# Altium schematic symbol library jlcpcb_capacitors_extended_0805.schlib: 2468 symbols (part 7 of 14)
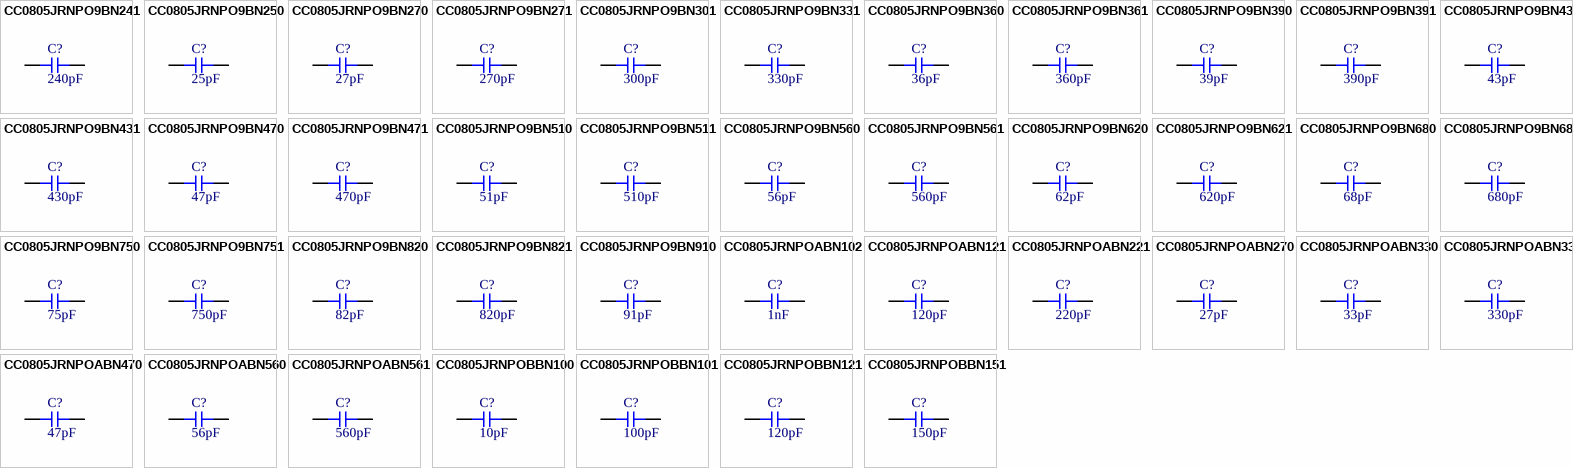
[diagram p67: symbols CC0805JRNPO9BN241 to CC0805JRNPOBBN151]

## CC0805JRNPO9BN511
designator C?  Capacitance: 510pF  (hidden comment: *)
Capacitor, Ceramic (MLCC), 510pF, ±5%, 50V, NP0, ±5%, SMD 0805; Manufacturer: YAGEO; Manufacturer Part Number: CC0805JRNPO9BN511
footprint CAP-0805 (0805 (2012M) Capacitor)
pins: 1, 2

## CC0805JRNPO9BN560
designator C?  Capacitance: 56pF  (hidden comment: *)
Capacitor, Ceramic (MLCC), 56pF, ±5%, 50V, NP0, ±5%, SMD 0805; Manufacturer: YAGEO; Manufacturer Part Number: CC0805JRNPO9BN560
footprint CAP-0805 (0805 (2012M) Capacitor)
pins: 1, 2

## CC0805JRNPO9BN561
designator C?  Capacitance: 560pF  (hidden comment: *)
Capacitor, Ceramic (MLCC), 560pF, ±5%, 50V, NP0, ±5%, SMD 0805; Manufacturer: YAGEO; Manufacturer Part Number: CC0805JRNPO9BN561
footprint CAP-0805 (0805 (2012M) Capacitor)
pins: 1, 2

## CC0805JRNPO9BN620
designator C?  Capacitance: 62pF  (hidden comment: *)
Capacitor, Ceramic (MLCC), 62pF, ±5%, 50V, NP0, ±5%, SMD 0805; Manufacturer: YAGEO; Manufacturer Part Number: CC0805JRNPO9BN620
footprint CAP-0805 (0805 (2012M) Capacitor)
pins: 1, 2

## CC0805JRNPO9BN621
designator C?  Capacitance: 620pF  (hidden comment: *)
Capacitor, Ceramic (MLCC), 620pF, ±5%, 50V, NP0, ±5%, SMD 0805; Manufacturer: YAGEO; Manufacturer Part Number: CC0805JRNPO9BN621
footprint CAP-0805 (0805 (2012M) Capacitor)
pins: 1, 2

## CC0805JRNPO9BN680
designator C?  Capacitance: 68pF  (hidden comment: *)
Capacitor, Ceramic (MLCC), 68pF, ±5%, 50V, NP0, ±5%, SMD 0805; Manufacturer: YAGEO; Manufacturer Part Number: CC0805JRNPO9BN680
footprint CAP-0805 (0805 (2012M) Capacitor)
pins: 1, 2

## CC0805JRNPO9BN681
designator C?  Capacitance: 680pF  (hidden comment: *)
Capacitor, Ceramic (MLCC), 680pF, ±5%, 50V, NP0, ±5%, SMD 0805; Manufacturer: YAGEO; Manufacturer Part Number: CC0805JRNPO9BN681
footprint CAP-0805 (0805 (2012M) Capacitor)
pins: 1, 2

## CC0805JRNPO9BN750
designator C?  Capacitance: 75pF  (hidden comment: *)
Capacitor, Ceramic (MLCC), 75pF, ±5%, 50V, NP0, ±5%, SMD 0805; Manufacturer: YAGEO; Manufacturer Part Number: CC0805JRNPO9BN750
footprint CAP-0805 (0805 (2012M) Capacitor)
pins: 1, 2

## CC0805JRNPO9BN751
designator C?  Capacitance: 750pF  (hidden comment: *)
Capacitor, Ceramic (MLCC), 750pF, ±5%, 50V, NP0, ±5%, SMD 0805; Manufacturer: YAGEO; Manufacturer Part Number: CC0805JRNPO9BN751
footprint CAP-0805 (0805 (2012M) Capacitor)
pins: 1, 2

## CC0805JRNPO9BN820
designator C?  Capacitance: 82pF  (hidden comment: *)
Capacitor, Ceramic (MLCC), 82pF, ±5%, 50V, NP0, ±5%, SMD 0805; Manufacturer: YAGEO; Manufacturer Part Number: CC0805JRNPO9BN820
footprint CAP-0805 (0805 (2012M) Capacitor)
pins: 1, 2

## CC0805JRNPO9BN821
designator C?  Capacitance: 820pF  (hidden comment: *)
Capacitor, Ceramic (MLCC), 820pF, ±5%, 50V, NP0, ±5%, SMD 0805; Manufacturer: YAGEO; Manufacturer Part Number: CC0805JRNPO9BN821
footprint CAP-0805 (0805 (2012M) Capacitor)
pins: 1, 2

## CC0805JRNPO9BN910
designator C?  Capacitance: 91pF  (hidden comment: *)
Capacitor, Ceramic (MLCC), 91pF, ±5%, 50V, NP0, ±5%, SMD 0805; Manufacturer: YAGEO; Manufacturer Part Number: CC0805JRNPO9BN910
footprint CAP-0805 (0805 (2012M) Capacitor)
pins: 1, 2

## CC0805JRNPOABN102
designator C?  Capacitance: 1nF  (hidden comment: *)
Capacitor, Ceramic (MLCC), 1nF, ±5%, 200V, NP0, ±5%, SMD 0805; Manufacturer: YAGEO; Manufacturer Part Number: CC0805JRNPOABN102
footprint CAP-0805 (0805 (2012M) Capacitor)
pins: 1, 2

## CC0805JRNPOABN121
designator C?  Capacitance: 120pF  (hidden comment: *)
Capacitor, Ceramic (MLCC), 120pF, ±5%, 200V, NP0, ±5%, SMD 0805; Manufacturer: YAGEO; Manufacturer Part Number: CC0805JRNPOABN121
footprint CAP-0805 (0805 (2012M) Capacitor)
pins: 1, 2

## CC0805JRNPOABN221
designator C?  Capacitance: 220pF  (hidden comment: *)
Capacitor, Ceramic (MLCC), 220pF, ±5%, 200V, NP0, ±5%, SMD 0805; Manufacturer: YAGEO; Manufacturer Part Number: CC0805JRNPOABN221
footprint CAP-0805 (0805 (2012M) Capacitor)
pins: 1, 2

## CC0805JRNPOABN270
designator C?  Capacitance: 27pF  (hidden comment: *)
Capacitor, Ceramic (MLCC), 27pF, ±5%, 200V, NP0, ±5%, SMD 0805; Manufacturer: YAGEO; Manufacturer Part Number: CC0805JRNPOABN270
footprint CAP-0805 (0805 (2012M) Capacitor)
pins: 1, 2

## CC0805JRNPOABN330
designator C?  Capacitance: 33pF  (hidden comment: *)
Capacitor, Ceramic (MLCC), 33pF, ±5%, 200V, NP0, ±5%, SMD 0805; Manufacturer: YAGEO; Manufacturer Part Number: CC0805JRNPOABN330
footprint CAP-0805 (0805 (2012M) Capacitor)
pins: 1, 2

## CC0805JRNPOABN331
designator C?  Capacitance: 330pF  (hidden comment: *)
Capacitor, Ceramic (MLCC), 330pF, ±5%, 200V, NP0, ±5%, SMD 0805; Manufacturer: YAGEO; Manufacturer Part Number: CC0805JRNPOABN331
footprint CAP-0805 (0805 (2012M) Capacitor)
pins: 1, 2

## CC0805JRNPOABN470
designator C?  Capacitance: 47pF  (hidden comment: *)
Capacitor, Ceramic (MLCC), 47pF, ±5%, 200V, NP0, ±5%, SMD 0805; Manufacturer: YAGEO; Manufacturer Part Number: CC0805JRNPOABN470
footprint CAP-0805 (0805 (2012M) Capacitor)
pins: 1, 2

## CC0805JRNPOABN560
designator C?  Capacitance: 56pF  (hidden comment: *)
Capacitor, Ceramic (MLCC), 56pF, ±5%, 200V, NP0, ±5%, SMD 0805; Manufacturer: YAGEO; Manufacturer Part Number: CC0805JRNPOABN560
footprint CAP-0805 (0805 (2012M) Capacitor)
pins: 1, 2

## CC0805JRNPOABN561
designator C?  Capacitance: 560pF  (hidden comment: *)
Capacitor, Ceramic (MLCC), 560pF, ±5%, 200V, NP0, ±5%, SMD 0805; Manufacturer: YAGEO; Manufacturer Part Number: CC0805JRNPOABN561
footprint CAP-0805 (0805 (2012M) Capacitor)
pins: 1, 2

## CC0805JRNPOBBN100
designator C?  Capacitance: 10pF  (hidden comment: *)
Capacitor, Ceramic (MLCC), 10pF, ±5%, 500V, NP0, ±5%, SMD 0805; Manufacturer: YAGEO; Manufacturer Part Number: CC0805JRNPOBBN100
footprint CAP-0805 (0805 (2012M) Capacitor)
pins: 1, 2

## CC0805JRNPOBBN101
designator C?  Capacitance: 100pF  (hidden comment: *)
Capacitor, Ceramic (MLCC), 100pF, ±5%, 500V, NP0, ±5%, SMD 0805; Manufacturer: YAGEO; Manufacturer Part Number: CC0805JRNPOBBN101
footprint CAP-0805 (0805 (2012M) Capacitor)
pins: 1, 2

## CC0805JRNPOBBN121
designator C?  Capacitance: 120pF  (hidden comment: *)
Capacitor, Ceramic (MLCC), 120pF, ±5%, 500V, NP0, ±5%, SMD 0805; Manufacturer: YAGEO; Manufacturer Part Number: CC0805JRNPOBBN121
footprint CAP-0805 (0805 (2012M) Capacitor)
pins: 1, 2

## CC0805JRNPOBBN151
designator C?  Capacitance: 150pF  (hidden comment: *)
Capacitor, Ceramic (MLCC), 150pF, ±5%, 500V, NP0, ±5%, SMD 0805; Manufacturer: YAGEO; Manufacturer Part Number: CC0805JRNPOBBN151
footprint CAP-0805 (0805 (2012M) Capacitor)
pins: 1, 2

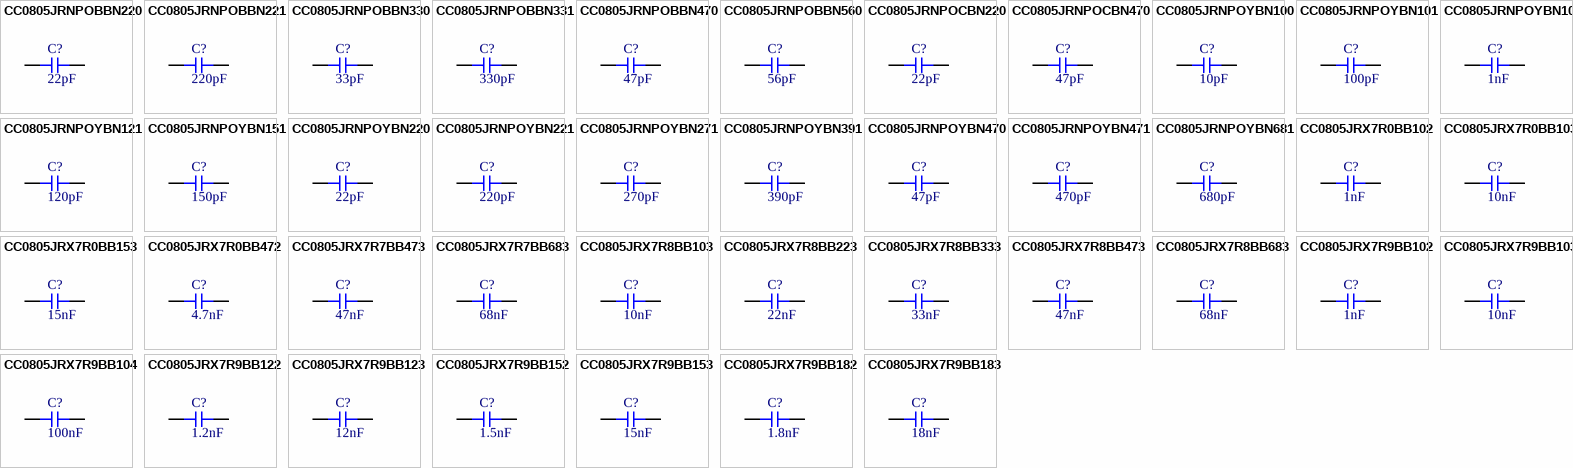
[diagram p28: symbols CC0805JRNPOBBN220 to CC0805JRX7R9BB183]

## CC0805JRNPOBBN220
designator C?  Capacitance: 22pF  (hidden comment: *)
Capacitor, Ceramic (MLCC), 22pF, ±5%, 500V, NP0, ±5%, SMD 0805; Manufacturer: YAGEO; Manufacturer Part Number: CC0805JRNPOBBN220
footprint CAP-0805 (0805 (2012M) Capacitor)
pins: 1, 2

## CC0805JRNPOBBN221
designator C?  Capacitance: 220pF  (hidden comment: *)
Capacitor, Ceramic (MLCC), 220pF, ±5%, 500V, NP0, ±5%, SMD 0805; Manufacturer: YAGEO; Manufacturer Part Number: CC0805JRNPOBBN221
footprint CAP-0805 (0805 (2012M) Capacitor)
pins: 1, 2

## CC0805JRNPOBBN330
designator C?  Capacitance: 33pF  (hidden comment: *)
Capacitor, Ceramic (MLCC), 33pF, ±5%, 500V, NP0, ±5%, SMD 0805; Manufacturer: YAGEO; Manufacturer Part Number: CC0805JRNPOBBN330
footprint CAP-0805 (0805 (2012M) Capacitor)
pins: 1, 2

## CC0805JRNPOBBN331
designator C?  Capacitance: 330pF  (hidden comment: *)
Capacitor, Ceramic (MLCC), 330pF, ±5%, 500V, NP0, ±5%, SMD 0805; Manufacturer: YAGEO; Manufacturer Part Number: CC0805JRNPOBBN331
footprint CAP-0805 (0805 (2012M) Capacitor)
pins: 1, 2

## CC0805JRNPOBBN470
designator C?  Capacitance: 47pF  (hidden comment: *)
Capacitor, Ceramic (MLCC), 47pF, ±5%, 500V, NP0, ±5%, SMD 0805; Manufacturer: YAGEO; Manufacturer Part Number: CC0805JRNPOBBN470
footprint CAP-0805 (0805 (2012M) Capacitor)
pins: 1, 2

## CC0805JRNPOBBN560
designator C?  Capacitance: 56pF  (hidden comment: *)
Capacitor, Ceramic (MLCC), 56pF, ±5%, 500V, NP0, ±5%, SMD 0805; Manufacturer: YAGEO; Manufacturer Part Number: CC0805JRNPOBBN560
footprint CAP-0805 (0805 (2012M) Capacitor)
pins: 1, 2

## CC0805JRNPOCBN220
designator C?  Capacitance: 22pF  (hidden comment: *)
Capacitor, Ceramic (MLCC), 22pF, ±5%, 1kV, NP0, ±5%, SMD 0805; Manufacturer: YAGEO; Manufacturer Part Number: CC0805JRNPOCBN220
footprint CAP-0805 (0805 (2012M) Capacitor)
pins: 1, 2

## CC0805JRNPOCBN470
designator C?  Capacitance: 47pF  (hidden comment: *)
Capacitor, Ceramic (MLCC), 47pF, ±5%, 1kV, NP0, ±5%, SMD 0805; Manufacturer: YAGEO; Manufacturer Part Number: CC0805JRNPOCBN470
footprint CAP-0805 (0805 (2012M) Capacitor)
pins: 1, 2

## CC0805JRNPOYBN100
designator C?  Capacitance: 10pF  (hidden comment: *)
Capacitor, Ceramic (MLCC), 10pF, ±5%, 250V, NP0, ±5%, SMD 0805; Manufacturer: YAGEO; Manufacturer Part Number: CC0805JRNPOYBN100
footprint CAP-0805 (0805 (2012M) Capacitor)
pins: 1, 2

## CC0805JRNPOYBN101
designator C?  Capacitance: 100pF  (hidden comment: *)
Capacitor, Ceramic (MLCC), 100pF, ±5%, 250V, NP0, ±5%, SMD 0805; Manufacturer: YAGEO; Manufacturer Part Number: CC0805JRNPOYBN101
footprint CAP-0805 (0805 (2012M) Capacitor)
pins: 1, 2

## CC0805JRNPOYBN102
designator C?  Capacitance: 1nF  (hidden comment: *)
Capacitor, Ceramic (MLCC), 1nF, ±5%, 250V, NP0, ±5%, SMD 0805; Manufacturer: YAGEO; Manufacturer Part Number: CC0805JRNPOYBN102
footprint CAP-0805 (0805 (2012M) Capacitor)
pins: 1, 2

## CC0805JRNPOYBN121
designator C?  Capacitance: 120pF  (hidden comment: *)
Capacitor, Ceramic (MLCC), 120pF, ±5%, 250V, NP0, ±5%, SMD 0805; Manufacturer: YAGEO; Manufacturer Part Number: CC0805JRNPOYBN121
footprint CAP-0805 (0805 (2012M) Capacitor)
pins: 1, 2

## CC0805JRNPOYBN151
designator C?  Capacitance: 150pF  (hidden comment: *)
Capacitor, Ceramic (MLCC), 150pF, ±5%, 250V, NP0, ±5%, SMD 0805; Manufacturer: YAGEO; Manufacturer Part Number: CC0805JRNPOYBN151
footprint CAP-0805 (0805 (2012M) Capacitor)
pins: 1, 2

## CC0805JRNPOYBN220
designator C?  Capacitance: 22pF  (hidden comment: *)
Capacitor, Ceramic (MLCC), 22pF, ±5%, 250V, NP0, ±5%, SMD 0805; Manufacturer: YAGEO; Manufacturer Part Number: CC0805JRNPOYBN220
footprint CAP-0805 (0805 (2012M) Capacitor)
pins: 1, 2

## CC0805JRNPOYBN221
designator C?  Capacitance: 220pF  (hidden comment: *)
Capacitor, Ceramic (MLCC), 220pF, ±5%, 250V, NP0, ±5%, SMD 0805; Manufacturer: YAGEO; Manufacturer Part Number: CC0805JRNPOYBN221
footprint CAP-0805 (0805 (2012M) Capacitor)
pins: 1, 2

## CC0805JRNPOYBN271
designator C?  Capacitance: 270pF  (hidden comment: *)
Capacitor, Ceramic (MLCC), 270pF, ±5%, 250V, NP0, ±5%, SMD 0805; Manufacturer: YAGEO; Manufacturer Part Number: CC0805JRNPOYBN271
footprint CAP-0805 (0805 (2012M) Capacitor)
pins: 1, 2

## CC0805JRNPOYBN391
designator C?  Capacitance: 390pF  (hidden comment: *)
Capacitor, Ceramic (MLCC), 390pF, ±5%, 250V, NP0, ±5%, SMD 0805; Manufacturer: YAGEO; Manufacturer Part Number: CC0805JRNPOYBN391
footprint CAP-0805 (0805 (2012M) Capacitor)
pins: 1, 2

## CC0805JRNPOYBN470
designator C?  Capacitance: 47pF  (hidden comment: *)
Capacitor, Ceramic (MLCC), 47pF, ±5%, 250V, NP0, ±5%, SMD 0805; Manufacturer: YAGEO; Manufacturer Part Number: CC0805JRNPOYBN470
footprint CAP-0805 (0805 (2012M) Capacitor)
pins: 1, 2

## CC0805JRNPOYBN471
designator C?  Capacitance: 470pF  (hidden comment: *)
Capacitor, Ceramic (MLCC), 470pF, ±5%, 250V, NP0, ±5%, SMD 0805; Manufacturer: YAGEO; Manufacturer Part Number: CC0805JRNPOYBN471
footprint CAP-0805 (0805 (2012M) Capacitor)
pins: 1, 2

## CC0805JRNPOYBN681
designator C?  Capacitance: 680pF  (hidden comment: *)
Capacitor, Ceramic (MLCC), 680pF, ±5%, 250V, NP0, ±5%, SMD 0805; Manufacturer: YAGEO; Manufacturer Part Number: CC0805JRNPOYBN681
footprint CAP-0805 (0805 (2012M) Capacitor)
pins: 1, 2

## CC0805JRX7R0BB102
designator C?  Capacitance: 1nF  (hidden comment: *)
Capacitor, Ceramic (MLCC), 1nF, ±5%, 100V, X7R, ±5%, SMD 0805; Manufacturer: YAGEO; Manufacturer Part Number: CC0805JRX7R0BB102
footprint CAP-0805 (0805 (2012M) Capacitor)
pins: 1, 2

## CC0805JRX7R0BB103
designator C?  Capacitance: 10nF  (hidden comment: *)
Capacitor, Ceramic (MLCC), 10nF, ±5%, 100V, X7R, ±5%, SMD 0805; Manufacturer: YAGEO; Manufacturer Part Number: CC0805JRX7R0BB103
footprint CAP-0805 (0805 (2012M) Capacitor)
pins: 1, 2

## CC0805JRX7R0BB153
designator C?  Capacitance: 15nF  (hidden comment: *)
Capacitor, Ceramic (MLCC), 15nF, ±5%, 100V, X7R, ±5%, SMD 0805; Manufacturer: YAGEO; Manufacturer Part Number: CC0805JRX7R0BB153
footprint CAP-0805 (0805 (2012M) Capacitor)
pins: 1, 2

## CC0805JRX7R0BB472
designator C?  Capacitance: 4.7nF  (hidden comment: *)
Capacitor, Ceramic (MLCC), 4.7nF, ±5%, 100V, X7R, ±5%, SMD 0805; Manufacturer: YAGEO; Manufacturer Part Number: CC0805JRX7R0BB472
footprint CAP-0805 (0805 (2012M) Capacitor)
pins: 1, 2

## CC0805JRX7R7BB473
designator C?  Capacitance: 47nF  (hidden comment: *)
Capacitor, Ceramic (MLCC), 47nF, ±5%, 16V, X7R, ±5%, SMD 0805; Manufacturer: YAGEO; Manufacturer Part Number: CC0805JRX7R7BB473
footprint CAP-0805 (0805 (2012M) Capacitor)
pins: 1, 2

## CC0805JRX7R7BB683
designator C?  Capacitance: 68nF  (hidden comment: *)
Capacitor, Ceramic (MLCC), 68nF, ±5%, 16V, X7R, ±5%, SMD 0805; Manufacturer: YAGEO; Manufacturer Part Number: CC0805JRX7R7BB683
footprint CAP-0805 (0805 (2012M) Capacitor)
pins: 1, 2

## CC0805JRX7R8BB103
designator C?  Capacitance: 10nF  (hidden comment: *)
Capacitor, Ceramic (MLCC), 10nF, ±5%, 25V, X7R, ±5%, SMD 0805; Manufacturer: YAGEO; Manufacturer Part Number: CC0805JRX7R8BB103
footprint CAP-0805 (0805 (2012M) Capacitor)
pins: 1, 2

## CC0805JRX7R8BB223
designator C?  Capacitance: 22nF  (hidden comment: *)
Capacitor, Ceramic (MLCC), 22nF, ±5%, 25V, X7R, ±5%, SMD 0805; Manufacturer: YAGEO; Manufacturer Part Number: CC0805JRX7R8BB223
footprint CAP-0805 (0805 (2012M) Capacitor)
pins: 1, 2

## CC0805JRX7R8BB333
designator C?  Capacitance: 33nF  (hidden comment: *)
Capacitor, Ceramic (MLCC), 33nF, ±5%, 25V, X7R, ±5%, SMD 0805; Manufacturer: YAGEO; Manufacturer Part Number: CC0805JRX7R8BB333
footprint CAP-0805 (0805 (2012M) Capacitor)
pins: 1, 2

## CC0805JRX7R8BB473
designator C?  Capacitance: 47nF  (hidden comment: *)
Capacitor, Ceramic (MLCC), 47nF, ±5%, 25V, X7R, ±5%, SMD 0805; Manufacturer: YAGEO; Manufacturer Part Number: CC0805JRX7R8BB473
footprint CAP-0805 (0805 (2012M) Capacitor)
pins: 1, 2

## CC0805JRX7R8BB683
designator C?  Capacitance: 68nF  (hidden comment: *)
Capacitor, Ceramic (MLCC), 68nF, ±5%, 25V, X7R, ±5%, SMD 0805; Manufacturer: YAGEO; Manufacturer Part Number: CC0805JRX7R8BB683
footprint CAP-0805 (0805 (2012M) Capacitor)
pins: 1, 2

## CC0805JRX7R9BB102
designator C?  Capacitance: 1nF  (hidden comment: *)
Capacitor, Ceramic (MLCC), 1nF, ±5%, 50V, X7R, ±5%, SMD 0805; Manufacturer: YAGEO; Manufacturer Part Number: CC0805JRX7R9BB102
footprint CAP-0805 (0805 (2012M) Capacitor)
pins: 1, 2

## CC0805JRX7R9BB103
designator C?  Capacitance: 10nF  (hidden comment: *)
Capacitor, Ceramic (MLCC), 10nF, ±5%, 50V, X7R, ±5%, SMD 0805; Manufacturer: YAGEO; Manufacturer Part Number: CC0805JRX7R9BB103
footprint CAP-0805 (0805 (2012M) Capacitor)
pins: 1, 2

## CC0805JRX7R9BB104
designator C?  Capacitance: 100nF  (hidden comment: *)
Capacitor, Ceramic (MLCC), 100nF, ±5%, 50V, X7R, ±5%, SMD 0805; Manufacturer: YAGEO; Manufacturer Part Number: CC0805JRX7R9BB104
footprint CAP-0805 (0805 (2012M) Capacitor)
pins: 1, 2

## CC0805JRX7R9BB122
designator C?  Capacitance: 1.2nF  (hidden comment: *)
Capacitor, Ceramic (MLCC), 1.2nF, ±5%, 50V, X7R, ±5%, SMD 0805; Manufacturer: YAGEO; Manufacturer Part Number: CC0805JRX7R9BB122
footprint CAP-0805 (0805 (2012M) Capacitor)
pins: 1, 2

## CC0805JRX7R9BB123
designator C?  Capacitance: 12nF  (hidden comment: *)
Capacitor, Ceramic (MLCC), 12nF, ±5%, 50V, X7R, ±5%, SMD 0805; Manufacturer: YAGEO; Manufacturer Part Number: CC0805JRX7R9BB123
footprint CAP-0805 (0805 (2012M) Capacitor)
pins: 1, 2

## CC0805JRX7R9BB152
designator C?  Capacitance: 1.5nF  (hidden comment: *)
Capacitor, Ceramic (MLCC), 1.5nF, ±5%, 50V, X7R, ±5%, SMD 0805; Manufacturer: YAGEO; Manufacturer Part Number: CC0805JRX7R9BB152
footprint CAP-0805 (0805 (2012M) Capacitor)
pins: 1, 2

## CC0805JRX7R9BB153
designator C?  Capacitance: 15nF  (hidden comment: *)
Capacitor, Ceramic (MLCC), 15nF, ±5%, 50V, X7R, ±5%, SMD 0805; Manufacturer: YAGEO; Manufacturer Part Number: CC0805JRX7R9BB153
footprint CAP-0805 (0805 (2012M) Capacitor)
pins: 1, 2

## CC0805JRX7R9BB182
designator C?  Capacitance: 1.8nF  (hidden comment: *)
Capacitor, Ceramic (MLCC), 1.8nF, ±5%, 50V, X7R, ±5%, SMD 0805; Manufacturer: YAGEO; Manufacturer Part Number: CC0805JRX7R9BB182
footprint CAP-0805 (0805 (2012M) Capacitor)
pins: 1, 2

## CC0805JRX7R9BB183
designator C?  Capacitance: 18nF  (hidden comment: *)
Capacitor, Ceramic (MLCC), 18nF, ±5%, 50V, X7R, ±5%, SMD 0805; Manufacturer: YAGEO; Manufacturer Part Number: CC0805JRX7R9BB183
footprint CAP-0805 (0805 (2012M) Capacitor)
pins: 1, 2

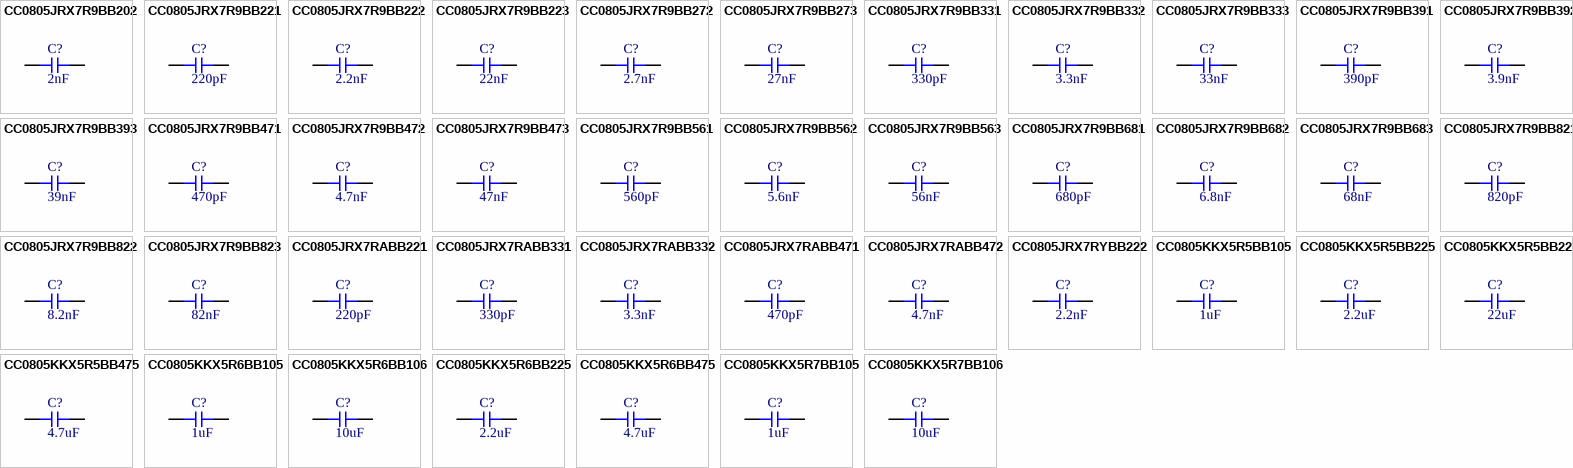
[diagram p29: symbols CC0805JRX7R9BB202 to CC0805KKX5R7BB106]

## CC0805JRX7R9BB202
designator C?  Capacitance: 2nF  (hidden comment: *)
Capacitor, Ceramic (MLCC), 2nF, ±5%, 50V, X7R, ±5%, SMD 0805; Manufacturer: YAGEO; Manufacturer Part Number: CC0805JRX7R9BB202
footprint CAP-0805 (0805 (2012M) Capacitor)
pins: 1, 2

## CC0805JRX7R9BB221
designator C?  Capacitance: 220pF  (hidden comment: *)
Capacitor, Ceramic (MLCC), 220pF, ±5%, 50V, X7R, ±5%, SMD 0805; Manufacturer: YAGEO; Manufacturer Part Number: CC0805JRX7R9BB221
footprint CAP-0805 (0805 (2012M) Capacitor)
pins: 1, 2

## CC0805JRX7R9BB222
designator C?  Capacitance: 2.2nF  (hidden comment: *)
Capacitor, Ceramic (MLCC), 2.2nF, ±5%, 50V, X7R, ±5%, SMD 0805; Manufacturer: YAGEO; Manufacturer Part Number: CC0805JRX7R9BB222
footprint CAP-0805 (0805 (2012M) Capacitor)
pins: 1, 2

## CC0805JRX7R9BB223
designator C?  Capacitance: 22nF  (hidden comment: *)
Capacitor, Ceramic (MLCC), 22nF, ±5%, 50V, X7R, ±5%, SMD 0805; Manufacturer: YAGEO; Manufacturer Part Number: CC0805JRX7R9BB223
footprint CAP-0805 (0805 (2012M) Capacitor)
pins: 1, 2

## CC0805JRX7R9BB272
designator C?  Capacitance: 2.7nF  (hidden comment: *)
Capacitor, Ceramic (MLCC), 2.7nF, ±5%, 50V, X7R, ±5%, SMD 0805; Manufacturer: YAGEO; Manufacturer Part Number: CC0805JRX7R9BB272
footprint CAP-0805 (0805 (2012M) Capacitor)
pins: 1, 2

## CC0805JRX7R9BB273
designator C?  Capacitance: 27nF  (hidden comment: *)
Capacitor, Ceramic (MLCC), 27nF, ±5%, 50V, X7R, ±5%, SMD 0805; Manufacturer: YAGEO; Manufacturer Part Number: CC0805JRX7R9BB273
footprint CAP-0805 (0805 (2012M) Capacitor)
pins: 1, 2

## CC0805JRX7R9BB331
designator C?  Capacitance: 330pF  (hidden comment: *)
Capacitor, Ceramic (MLCC), 330pF, ±5%, 50V, X7R, ±5%, SMD 0805; Manufacturer: YAGEO; Manufacturer Part Number: CC0805JRX7R9BB331
footprint CAP-0805 (0805 (2012M) Capacitor)
pins: 1, 2

## CC0805JRX7R9BB332
designator C?  Capacitance: 3.3nF  (hidden comment: *)
Capacitor, Ceramic (MLCC), 3.3nF, ±5%, 50V, X7R, ±5%, SMD 0805; Manufacturer: YAGEO; Manufacturer Part Number: CC0805JRX7R9BB332
footprint CAP-0805 (0805 (2012M) Capacitor)
pins: 1, 2

## CC0805JRX7R9BB333
designator C?  Capacitance: 33nF  (hidden comment: *)
Capacitor, Ceramic (MLCC), 33nF, ±5%, 50V, X7R, ±5%, SMD 0805; Manufacturer: YAGEO; Manufacturer Part Number: CC0805JRX7R9BB333
footprint CAP-0805 (0805 (2012M) Capacitor)
pins: 1, 2

## CC0805JRX7R9BB391
designator C?  Capacitance: 390pF  (hidden comment: *)
Capacitor, Ceramic (MLCC), 390pF, ±5%, 50V, X7R, ±5%, SMD 0805; Manufacturer: YAGEO; Manufacturer Part Number: CC0805JRX7R9BB391
footprint CAP-0805 (0805 (2012M) Capacitor)
pins: 1, 2

## CC0805JRX7R9BB392
designator C?  Capacitance: 3.9nF  (hidden comment: *)
Capacitor, Ceramic (MLCC), 3.9nF, ±5%, 50V, X7R, ±5%, SMD 0805; Manufacturer: YAGEO; Manufacturer Part Number: CC0805JRX7R9BB392
footprint CAP-0805 (0805 (2012M) Capacitor)
pins: 1, 2

## CC0805JRX7R9BB393
designator C?  Capacitance: 39nF  (hidden comment: *)
Capacitor, Ceramic (MLCC), 39nF, ±5%, 50V, X7R, ±5%, SMD 0805; Manufacturer: YAGEO; Manufacturer Part Number: CC0805JRX7R9BB393
footprint CAP-0805 (0805 (2012M) Capacitor)
pins: 1, 2

## CC0805JRX7R9BB471
designator C?  Capacitance: 470pF  (hidden comment: *)
Capacitor, Ceramic (MLCC), 470pF, ±5%, 50V, X7R, ±5%, SMD 0805; Manufacturer: YAGEO; Manufacturer Part Number: CC0805JRX7R9BB471
footprint CAP-0805 (0805 (2012M) Capacitor)
pins: 1, 2

## CC0805JRX7R9BB472
designator C?  Capacitance: 4.7nF  (hidden comment: *)
Capacitor, Ceramic (MLCC), 4.7nF, ±5%, 50V, X7R, ±5%, SMD 0805; Manufacturer: YAGEO; Manufacturer Part Number: CC0805JRX7R9BB472
footprint CAP-0805 (0805 (2012M) Capacitor)
pins: 1, 2

## CC0805JRX7R9BB473
designator C?  Capacitance: 47nF  (hidden comment: *)
Capacitor, Ceramic (MLCC), 47nF, ±5%, 50V, X7R, ±5%, SMD 0805; Manufacturer: YAGEO; Manufacturer Part Number: CC0805JRX7R9BB473
footprint CAP-0805 (0805 (2012M) Capacitor)
pins: 1, 2

## CC0805JRX7R9BB561
designator C?  Capacitance: 560pF  (hidden comment: *)
Capacitor, Ceramic (MLCC), 560pF, ±5%, 50V, X7R, ±5%, SMD 0805; Manufacturer: YAGEO; Manufacturer Part Number: CC0805JRX7R9BB561
footprint CAP-0805 (0805 (2012M) Capacitor)
pins: 1, 2

## CC0805JRX7R9BB562
designator C?  Capacitance: 5.6nF  (hidden comment: *)
Capacitor, Ceramic (MLCC), 5.6nF, ±5%, 50V, X7R, ±5%, SMD 0805; Manufacturer: YAGEO; Manufacturer Part Number: CC0805JRX7R9BB562
footprint CAP-0805 (0805 (2012M) Capacitor)
pins: 1, 2

## CC0805JRX7R9BB563
designator C?  Capacitance: 56nF  (hidden comment: *)
Capacitor, Ceramic (MLCC), 56nF, ±5%, 50V, X7R, ±5%, SMD 0805; Manufacturer: YAGEO; Manufacturer Part Number: CC0805JRX7R9BB563
footprint CAP-0805 (0805 (2012M) Capacitor)
pins: 1, 2

## CC0805JRX7R9BB681
designator C?  Capacitance: 680pF  (hidden comment: *)
Capacitor, Ceramic (MLCC), 680pF, ±5%, 50V, X7R, ±5%, SMD 0805; Manufacturer: YAGEO; Manufacturer Part Number: CC0805JRX7R9BB681
footprint CAP-0805 (0805 (2012M) Capacitor)
pins: 1, 2

## CC0805JRX7R9BB682
designator C?  Capacitance: 6.8nF  (hidden comment: *)
Capacitor, Ceramic (MLCC), 6.8nF, ±5%, 50V, X7R, ±5%, SMD 0805; Manufacturer: YAGEO; Manufacturer Part Number: CC0805JRX7R9BB682
footprint CAP-0805 (0805 (2012M) Capacitor)
pins: 1, 2

## CC0805JRX7R9BB683
designator C?  Capacitance: 68nF  (hidden comment: *)
Capacitor, Ceramic (MLCC), 68nF, ±5%, 50V, X7R, ±5%, SMD 0805; Manufacturer: YAGEO; Manufacturer Part Number: CC0805JRX7R9BB683
footprint CAP-0805 (0805 (2012M) Capacitor)
pins: 1, 2

## CC0805JRX7R9BB821
designator C?  Capacitance: 820pF  (hidden comment: *)
Capacitor, Ceramic (MLCC), 820pF, ±5%, 50V, X7R, ±5%, SMD 0805; Manufacturer: YAGEO; Manufacturer Part Number: CC0805JRX7R9BB821
footprint CAP-0805 (0805 (2012M) Capacitor)
pins: 1, 2

## CC0805JRX7R9BB822
designator C?  Capacitance: 8.2nF  (hidden comment: *)
Capacitor, Ceramic (MLCC), 8.2nF, ±5%, 50V, X7R, ±5%, SMD 0805; Manufacturer: YAGEO; Manufacturer Part Number: CC0805JRX7R9BB822
footprint CAP-0805 (0805 (2012M) Capacitor)
pins: 1, 2

## CC0805JRX7R9BB823
designator C?  Capacitance: 82nF  (hidden comment: *)
Capacitor, Ceramic (MLCC), 82nF, ±5%, 50V, X7R, ±5%, SMD 0805; Manufacturer: YAGEO; Manufacturer Part Number: CC0805JRX7R9BB823
footprint CAP-0805 (0805 (2012M) Capacitor)
pins: 1, 2

## CC0805JRX7RABB221
designator C?  Capacitance: 220pF  (hidden comment: *)
Capacitor, Ceramic (MLCC), 220pF, ±5%, 200V, X7R, ±5%, SMD 0805; Manufacturer: YAGEO; Manufacturer Part Number: CC0805JRX7RABB221
footprint CAP-0805 (0805 (2012M) Capacitor)
pins: 1, 2

## CC0805JRX7RABB331
designator C?  Capacitance: 330pF  (hidden comment: *)
Capacitor, Ceramic (MLCC), 330pF, ±5%, 200V, X7R, ±5%, SMD 0805; Manufacturer: YAGEO; Manufacturer Part Number: CC0805JRX7RABB331
footprint CAP-0805 (0805 (2012M) Capacitor)
pins: 1, 2

## CC0805JRX7RABB332
designator C?  Capacitance: 3.3nF  (hidden comment: *)
Capacitor, Ceramic (MLCC), 3.3nF, ±5%, 200V, X7R, ±5%, SMD 0805; Manufacturer: YAGEO; Manufacturer Part Number: CC0805JRX7RABB332
footprint CAP-0805 (0805 (2012M) Capacitor)
pins: 1, 2

## CC0805JRX7RABB471
designator C?  Capacitance: 470pF  (hidden comment: *)
Capacitor, Ceramic (MLCC), 470pF, ±5%, 200V, X7R, ±5%, SMD 0805; Manufacturer: YAGEO; Manufacturer Part Number: CC0805JRX7RABB471
footprint CAP-0805 (0805 (2012M) Capacitor)
pins: 1, 2

## CC0805JRX7RABB472
designator C?  Capacitance: 4.7nF  (hidden comment: *)
Capacitor, Ceramic (MLCC), 4.7nF, ±5%, 200V, X7R, ±5%, SMD 0805; Manufacturer: YAGEO; Manufacturer Part Number: CC0805JRX7RABB472
footprint CAP-0805 (0805 (2012M) Capacitor)
pins: 1, 2

## CC0805JRX7RYBB222
designator C?  Capacitance: 2.2nF  (hidden comment: *)
Capacitor, Ceramic (MLCC), 2.2nF, ±5%, 250V, X7R, ±5%, SMD 0805; Manufacturer: YAGEO; Manufacturer Part Number: CC0805JRX7RYBB222
footprint CAP-0805 (0805 (2012M) Capacitor)
pins: 1, 2

## CC0805KKX5R5BB105
designator C?  Capacitance: 1uF  (hidden comment: *)
Capacitor, Ceramic (MLCC), 1uF, ±10%, 6.3V, X5R, ±10%, SMD 0805; Manufacturer: YAGEO; Manufacturer Part Number: CC0805KKX5R5BB105
footprint CAP-0805 (0805 (2012M) Capacitor)
pins: 1, 2

## CC0805KKX5R5BB225
designator C?  Capacitance: 2.2uF  (hidden comment: *)
Capacitor, Ceramic (MLCC), 2.2uF, ±10%, 6.3V, X5R, ±10%, SMD 0805; Manufacturer: YAGEO; Manufacturer Part Number: CC0805KKX5R5BB225
footprint CAP-0805 (0805 (2012M) Capacitor)
pins: 1, 2

## CC0805KKX5R5BB226
designator C?  Capacitance: 22uF  (hidden comment: *)
Capacitor, Ceramic (MLCC), 22uF, ±10%, 6.3V, X5R, ±10%, SMD 0805; Manufacturer: YAGEO; Manufacturer Part Number: CC0805KKX5R5BB226
footprint CAP-0805 (0805 (2012M) Capacitor)
pins: 1, 2

## CC0805KKX5R5BB475
designator C?  Capacitance: 4.7uF  (hidden comment: *)
Capacitor, Ceramic (MLCC), 4.7uF, ±10%, 6.3V, X5R, ±10%, SMD 0805; Manufacturer: YAGEO; Manufacturer Part Number: CC0805KKX5R5BB475
footprint CAP-0805 (0805 (2012M) Capacitor)
pins: 1, 2

## CC0805KKX5R6BB105
designator C?  Capacitance: 1uF  (hidden comment: *)
Capacitor, Ceramic (MLCC), 1uF, ±10%, 10V, X5R, ±10%, SMD 0805; Manufacturer: YAGEO; Manufacturer Part Number: CC0805KKX5R6BB105
footprint CAP-0805 (0805 (2012M) Capacitor)
pins: 1, 2

## CC0805KKX5R6BB106
designator C?  Capacitance: 10uF  (hidden comment: *)
Capacitor, Ceramic (MLCC), 10uF, ±10%, 10V, X5R, ±10%, SMD 0805; Manufacturer: YAGEO; Manufacturer Part Number: CC0805KKX5R6BB106
footprint CAP-0805 (0805 (2012M) Capacitor)
pins: 1, 2

## CC0805KKX5R6BB225
designator C?  Capacitance: 2.2uF  (hidden comment: *)
Capacitor, Ceramic (MLCC), 2.2uF, ±10%, 10V, X5R, ±10%, SMD 0805; Manufacturer: YAGEO; Manufacturer Part Number: CC0805KKX5R6BB225
footprint CAP-0805 (0805 (2012M) Capacitor)
pins: 1, 2

## CC0805KKX5R6BB475
designator C?  Capacitance: 4.7uF  (hidden comment: *)
Capacitor, Ceramic (MLCC), 4.7uF, ±10%, 10V, X5R, ±10%, SMD 0805; Manufacturer: YAGEO; Manufacturer Part Number: CC0805KKX5R6BB475
footprint CAP-0805 (0805 (2012M) Capacitor)
pins: 1, 2

## CC0805KKX5R7BB105
designator C?  Capacitance: 1uF  (hidden comment: *)
Capacitor, Ceramic (MLCC), 1uF, ±10%, 16V, X5R, ±10%, SMD 0805; Manufacturer: YAGEO; Manufacturer Part Number: CC0805KKX5R7BB105
footprint CAP-0805 (0805 (2012M) Capacitor)
pins: 1, 2

## CC0805KKX5R7BB106
designator C?  Capacitance: 10uF  (hidden comment: *)
Capacitor, Ceramic (MLCC), 10uF, ±10%, 16V, X5R, ±10%, SMD 0805; Manufacturer: YAGEO; Manufacturer Part Number: CC0805KKX5R7BB106
footprint CAP-0805 (0805 (2012M) Capacitor)
pins: 1, 2

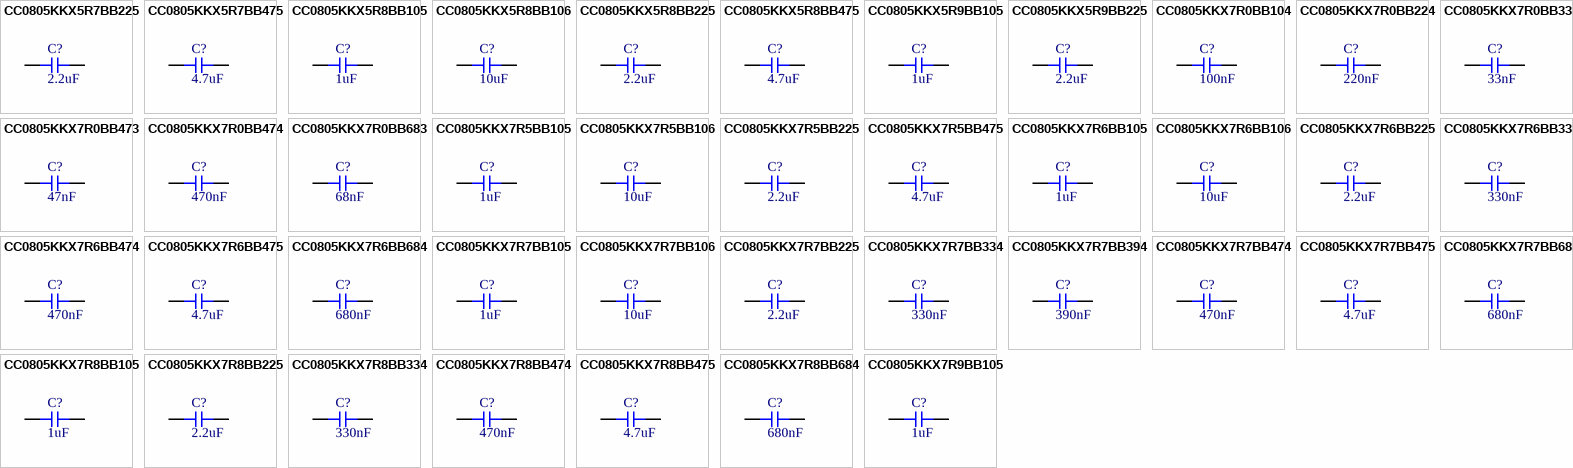
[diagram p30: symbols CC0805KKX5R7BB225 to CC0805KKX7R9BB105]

## CC0805KKX5R7BB225
designator C?  Capacitance: 2.2uF  (hidden comment: *)
Capacitor, Ceramic (MLCC), 2.2uF, ±10%, 16V, X5R, ±10%, SMD 0805; Manufacturer: YAGEO; Manufacturer Part Number: CC0805KKX5R7BB225
footprint CAP-0805 (0805 (2012M) Capacitor)
pins: 1, 2

## CC0805KKX5R7BB475
designator C?  Capacitance: 4.7uF  (hidden comment: *)
Capacitor, Ceramic (MLCC), 4.7uF, ±10%, 16V, X5R, ±10%, SMD 0805; Manufacturer: YAGEO; Manufacturer Part Number: CC0805KKX5R7BB475
footprint CAP-0805 (0805 (2012M) Capacitor)
pins: 1, 2

## CC0805KKX5R8BB105
designator C?  Capacitance: 1uF  (hidden comment: *)
Capacitor, Ceramic (MLCC), 1uF, ±10%, 25V, X5R, ±10%, SMD 0805; Manufacturer: YAGEO; Manufacturer Part Number: CC0805KKX5R8BB105
footprint CAP-0805 (0805 (2012M) Capacitor)
pins: 1, 2

## CC0805KKX5R8BB106
designator C?  Capacitance: 10uF  (hidden comment: *)
Capacitor, Ceramic (MLCC), 10uF, ±10%, 25V, X5R, ±10%, SMD 0805; Manufacturer: YAGEO; Manufacturer Part Number: CC0805KKX5R8BB106
footprint CAP-0805 (0805 (2012M) Capacitor)
pins: 1, 2

## CC0805KKX5R8BB225
designator C?  Capacitance: 2.2uF  (hidden comment: *)
Capacitor, Ceramic (MLCC), 2.2uF, ±10%, 25V, X5R, ±10%, SMD 0805; Manufacturer: YAGEO; Manufacturer Part Number: CC0805KKX5R8BB225
footprint CAP-0805 (0805 (2012M) Capacitor)
pins: 1, 2

## CC0805KKX5R8BB475
designator C?  Capacitance: 4.7uF  (hidden comment: *)
Capacitor, Ceramic (MLCC), 4.7uF, ±10%, 25V, X5R, ±10%, SMD 0805; Manufacturer: YAGEO; Manufacturer Part Number: CC0805KKX5R8BB475
footprint CAP-0805 (0805 (2012M) Capacitor)
pins: 1, 2

## CC0805KKX5R9BB105
designator C?  Capacitance: 1uF  (hidden comment: *)
Capacitor, Ceramic (MLCC), 1uF, ±10%, 50V, X5R, ±10%, SMD 0805; Manufacturer: YAGEO; Manufacturer Part Number: CC0805KKX5R9BB105
footprint CAP-0805 (0805 (2012M) Capacitor)
pins: 1, 2

## CC0805KKX5R9BB225
designator C?  Capacitance: 2.2uF  (hidden comment: *)
Capacitor, Ceramic (MLCC), 2.2uF, ±10%, 50V, X5R, ±10%, SMD 0805; Manufacturer: YAGEO; Manufacturer Part Number: CC0805KKX5R9BB225
footprint CAP-0805 (0805 (2012M) Capacitor)
pins: 1, 2

## CC0805KKX7R0BB104
designator C?  Capacitance: 100nF  (hidden comment: *)
Capacitor, Ceramic (MLCC), 100nF, ±10%, 100V, X7R, ±10%, SMD 0805; Manufacturer: YAGEO; Manufacturer Part Number: CC0805KKX7R0BB104
footprint CAP-0805 (0805 (2012M) Capacitor)
pins: 1, 2

## CC0805KKX7R0BB224
designator C?  Capacitance: 220nF  (hidden comment: *)
Capacitor, Ceramic (MLCC), 220nF, ±10%, 100V, X7R, ±10%, SMD 0805; Manufacturer: YAGEO; Manufacturer Part Number: CC0805KKX7R0BB224
footprint CAP-0805 (0805 (2012M) Capacitor)
pins: 1, 2

## CC0805KKX7R0BB333
designator C?  Capacitance: 33nF  (hidden comment: *)
Capacitor, Ceramic (MLCC), 33nF, ±10%, 100V, X7R, ±10%, SMD 0805; Manufacturer: YAGEO; Manufacturer Part Number: CC0805KKX7R0BB333
footprint CAP-0805 (0805 (2012M) Capacitor)
pins: 1, 2

## CC0805KKX7R0BB473
designator C?  Capacitance: 47nF  (hidden comment: *)
Capacitor, Ceramic (MLCC), 47nF, ±10%, 100V, X7R, ±10%, SMD 0805; Manufacturer: YAGEO; Manufacturer Part Number: CC0805KKX7R0BB473
footprint CAP-0805 (0805 (2012M) Capacitor)
pins: 1, 2

## CC0805KKX7R0BB474
designator C?  Capacitance: 470nF  (hidden comment: *)
Capacitor, Ceramic (MLCC), 470nF, ±10%, 100V, X7R, ±10%, SMD 0805; Manufacturer: YAGEO; Manufacturer Part Number: CC0805KKX7R0BB474
footprint CAP-0805 (0805 (2012M) Capacitor)
pins: 1, 2

## CC0805KKX7R0BB683
designator C?  Capacitance: 68nF  (hidden comment: *)
Capacitor, Ceramic (MLCC), 68nF, ±10%, 100V, X7R, ±10%, SMD 0805; Manufacturer: YAGEO; Manufacturer Part Number: CC0805KKX7R0BB683
footprint CAP-0805 (0805 (2012M) Capacitor)
pins: 1, 2

## CC0805KKX7R5BB105
designator C?  Capacitance: 1uF  (hidden comment: *)
Capacitor, Ceramic (MLCC), 1uF, ±10%, 6.3V, X7R, ±10%, SMD 0805; Manufacturer: YAGEO; Manufacturer Part Number: CC0805KKX7R5BB105
footprint CAP-0805 (0805 (2012M) Capacitor)
pins: 1, 2

## CC0805KKX7R5BB106
designator C?  Capacitance: 10uF  (hidden comment: *)
Capacitor, Ceramic (MLCC), 10uF, ±10%, 6.3V, X7R, ±10%, SMD 0805; Manufacturer: YAGEO; Manufacturer Part Number: CC0805KKX7R5BB106
footprint CAP-0805 (0805 (2012M) Capacitor)
pins: 1, 2

## CC0805KKX7R5BB225
designator C?  Capacitance: 2.2uF  (hidden comment: *)
Capacitor, Ceramic (MLCC), 2.2uF, ±10%, 6.3V, X7R, ±10%, SMD 0805; Manufacturer: YAGEO; Manufacturer Part Number: CC0805KKX7R5BB225
footprint CAP-0805 (0805 (2012M) Capacitor)
pins: 1, 2

## CC0805KKX7R5BB475
designator C?  Capacitance: 4.7uF  (hidden comment: *)
Capacitor, Ceramic (MLCC), 4.7uF, ±10%, 6.3V, X7R, ±10%, SMD 0805; Manufacturer: YAGEO; Manufacturer Part Number: CC0805KKX7R5BB475
footprint CAP-0805 (0805 (2012M) Capacitor)
pins: 1, 2

## CC0805KKX7R6BB105
designator C?  Capacitance: 1uF  (hidden comment: *)
Capacitor, Ceramic (MLCC), 1uF, ±10%, 10V, X7R, ±10%, SMD 0805; Manufacturer: YAGEO; Manufacturer Part Number: CC0805KKX7R6BB105
footprint CAP-0805 (0805 (2012M) Capacitor)
pins: 1, 2

## CC0805KKX7R6BB106
designator C?  Capacitance: 10uF  (hidden comment: *)
Capacitor, Ceramic (MLCC), 10uF, ±10%, 10V, X7R, ±10%, SMD 0805; Manufacturer: YAGEO; Manufacturer Part Number: CC0805KKX7R6BB106
footprint CAP-0805 (0805 (2012M) Capacitor)
pins: 1, 2

## CC0805KKX7R6BB225
designator C?  Capacitance: 2.2uF  (hidden comment: *)
Capacitor, Ceramic (MLCC), 2.2uF, ±10%, 10V, X7R, ±10%, SMD 0805; Manufacturer: YAGEO; Manufacturer Part Number: CC0805KKX7R6BB225
footprint CAP-0805 (0805 (2012M) Capacitor)
pins: 1, 2

## CC0805KKX7R6BB334
designator C?  Capacitance: 330nF  (hidden comment: *)
Capacitor, Ceramic (MLCC), 330nF, ±10%, 10V, X7R, ±10%, SMD 0805; Manufacturer: YAGEO; Manufacturer Part Number: CC0805KKX7R6BB334
footprint CAP-0805 (0805 (2012M) Capacitor)
pins: 1, 2

## CC0805KKX7R6BB474
designator C?  Capacitance: 470nF  (hidden comment: *)
Capacitor, Ceramic (MLCC), 470nF, ±10%, 10V, X7R, ±10%, SMD 0805; Manufacturer: YAGEO; Manufacturer Part Number: CC0805KKX7R6BB474
footprint CAP-0805 (0805 (2012M) Capacitor)
pins: 1, 2

## CC0805KKX7R6BB475
designator C?  Capacitance: 4.7uF  (hidden comment: *)
Capacitor, Ceramic (MLCC), 4.7uF, ±10%, 10V, X7R, ±10%, SMD 0805; Manufacturer: YAGEO; Manufacturer Part Number: CC0805KKX7R6BB475
footprint CAP-0805 (0805 (2012M) Capacitor)
pins: 1, 2

## CC0805KKX7R6BB684
designator C?  Capacitance: 680nF  (hidden comment: *)
Capacitor, Ceramic (MLCC), 680nF, ±10%, 10V, X7R, ±10%, SMD 0805; Manufacturer: YAGEO; Manufacturer Part Number: CC0805KKX7R6BB684
footprint CAP-0805 (0805 (2012M) Capacitor)
pins: 1, 2

## CC0805KKX7R7BB105
designator C?  Capacitance: 1uF  (hidden comment: *)
Capacitor, Ceramic (MLCC), 1uF, ±10%, 16V, X7R, ±10%, SMD 0805; Manufacturer: YAGEO; Manufacturer Part Number: CC0805KKX7R7BB105
footprint CAP-0805 (0805 (2012M) Capacitor)
pins: 1, 2

## CC0805KKX7R7BB106
designator C?  Capacitance: 10uF  (hidden comment: *)
Capacitor, Ceramic (MLCC), 10uF, ±10%, 16V, X7R, ±10%, SMD 0805; Manufacturer: YAGEO; Manufacturer Part Number: CC0805KKX7R7BB106
footprint CAP-0805 (0805 (2012M) Capacitor)
pins: 1, 2

## CC0805KKX7R7BB225
designator C?  Capacitance: 2.2uF  (hidden comment: *)
Capacitor, Ceramic (MLCC), 2.2uF, ±10%, 16V, X7R, ±10%, SMD 0805; Manufacturer: YAGEO; Manufacturer Part Number: CC0805KKX7R7BB225
footprint CAP-0805 (0805 (2012M) Capacitor)
pins: 1, 2

## CC0805KKX7R7BB334
designator C?  Capacitance: 330nF  (hidden comment: *)
Capacitor, Ceramic (MLCC), 330nF, ±10%, 16V, X7R, ±10%, SMD 0805; Manufacturer: YAGEO; Manufacturer Part Number: CC0805KKX7R7BB334
footprint CAP-0805 (0805 (2012M) Capacitor)
pins: 1, 2

## CC0805KKX7R7BB394
designator C?  Capacitance: 390nF  (hidden comment: *)
Capacitor, Ceramic (MLCC), 390nF, ±10%, 16V, X7R, ±10%, SMD 0805; Manufacturer: YAGEO; Manufacturer Part Number: CC0805KKX7R7BB394
footprint CAP-0805 (0805 (2012M) Capacitor)
pins: 1, 2

## CC0805KKX7R7BB474
designator C?  Capacitance: 470nF  (hidden comment: *)
Capacitor, Ceramic (MLCC), 470nF, ±10%, 16V, X7R, ±10%, SMD 0805; Manufacturer: YAGEO; Manufacturer Part Number: CC0805KKX7R7BB474
footprint CAP-0805 (0805 (2012M) Capacitor)
pins: 1, 2

## CC0805KKX7R7BB475
designator C?  Capacitance: 4.7uF  (hidden comment: *)
Capacitor, Ceramic (MLCC), 4.7uF, ±10%, 16V, X7R, ±10%, SMD 0805; Manufacturer: YAGEO; Manufacturer Part Number: CC0805KKX7R7BB475
footprint CAP-0805 (0805 (2012M) Capacitor)
pins: 1, 2

## CC0805KKX7R7BB684
designator C?  Capacitance: 680nF  (hidden comment: *)
Capacitor, Ceramic (MLCC), 680nF, ±10%, 16V, X7R, ±10%, SMD 0805; Manufacturer: YAGEO; Manufacturer Part Number: CC0805KKX7R7BB684
footprint CAP-0805 (0805 (2012M) Capacitor)
pins: 1, 2

## CC0805KKX7R8BB105
designator C?  Capacitance: 1uF  (hidden comment: *)
Capacitor, Ceramic (MLCC), 1uF, ±10%, 25V, X7R, ±10%, SMD 0805; Manufacturer: YAGEO; Manufacturer Part Number: CC0805KKX7R8BB105
footprint CAP-0805 (0805 (2012M) Capacitor)
pins: 1, 2

## CC0805KKX7R8BB225
designator C?  Capacitance: 2.2uF  (hidden comment: *)
Capacitor, Ceramic (MLCC), 2.2uF, ±10%, 25V, X7R, ±10%, SMD 0805; Manufacturer: YAGEO; Manufacturer Part Number: CC0805KKX7R8BB225
footprint CAP-0805 (0805 (2012M) Capacitor)
pins: 1, 2

## CC0805KKX7R8BB334
designator C?  Capacitance: 330nF  (hidden comment: *)
Capacitor, Ceramic (MLCC), 330nF, ±10%, 25V, X7R, ±10%, SMD 0805; Manufacturer: YAGEO; Manufacturer Part Number: CC0805KKX7R8BB334
footprint CAP-0805 (0805 (2012M) Capacitor)
pins: 1, 2

## CC0805KKX7R8BB474
designator C?  Capacitance: 470nF  (hidden comment: *)
Capacitor, Ceramic (MLCC), 470nF, ±10%, 25V, X7R, ±10%, SMD 0805; Manufacturer: YAGEO; Manufacturer Part Number: CC0805KKX7R8BB474
footprint CAP-0805 (0805 (2012M) Capacitor)
pins: 1, 2

## CC0805KKX7R8BB475
designator C?  Capacitance: 4.7uF  (hidden comment: *)
Capacitor, Ceramic (MLCC), 4.7uF, ±10%, 25V, X7R, ±10%, SMD 0805; Manufacturer: YAGEO; Manufacturer Part Number: CC0805KKX7R8BB475
footprint CAP-0805 (0805 (2012M) Capacitor)
pins: 1, 2

## CC0805KKX7R8BB684
designator C?  Capacitance: 680nF  (hidden comment: *)
Capacitor, Ceramic (MLCC), 680nF, ±10%, 25V, X7R, ±10%, SMD 0805; Manufacturer: YAGEO; Manufacturer Part Number: CC0805KKX7R8BB684
footprint CAP-0805 (0805 (2012M) Capacitor)
pins: 1, 2

## CC0805KKX7R9BB105
designator C?  Capacitance: 1uF  (hidden comment: *)
Capacitor, Ceramic (MLCC), 1uF, ±10%, 50V, X7R, ±10%, SMD 0805; Manufacturer: YAGEO; Manufacturer Part Number: CC0805KKX7R9BB105
footprint CAP-0805 (0805 (2012M) Capacitor)
pins: 1, 2

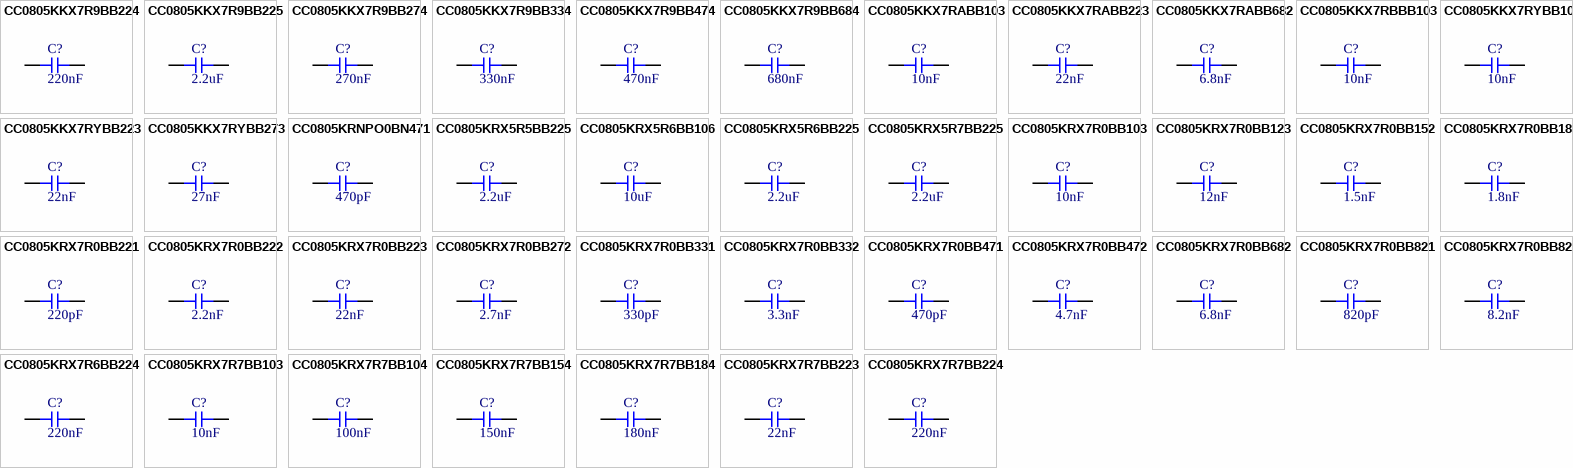
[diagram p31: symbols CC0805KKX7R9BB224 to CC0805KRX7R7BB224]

## CC0805KKX7R9BB224
designator C?  Capacitance: 220nF  (hidden comment: *)
Capacitor, Ceramic (MLCC), 220nF, ±10%, 50V, X7R, ±10%, SMD 0805; Manufacturer: YAGEO; Manufacturer Part Number: CC0805KKX7R9BB224
footprint CAP-0805 (0805 (2012M) Capacitor)
pins: 1, 2

## CC0805KKX7R9BB225
designator C?  Capacitance: 2.2uF  (hidden comment: *)
Capacitor, Ceramic (MLCC), 2.2uF, ±10%, 50V, X7R, ±10%, SMD 0805; Manufacturer: YAGEO; Manufacturer Part Number: CC0805KKX7R9BB225
footprint CAP-0805 (0805 (2012M) Capacitor)
pins: 1, 2

## CC0805KKX7R9BB274
designator C?  Capacitance: 270nF  (hidden comment: *)
Capacitor, Ceramic (MLCC), 270nF, ±10%, 50V, X7R, ±10%, SMD 0805; Manufacturer: YAGEO; Manufacturer Part Number: CC0805KKX7R9BB274
footprint CAP-0805 (0805 (2012M) Capacitor)
pins: 1, 2

## CC0805KKX7R9BB334
designator C?  Capacitance: 330nF  (hidden comment: *)
Capacitor, Ceramic (MLCC), 330nF, ±10%, 50V, X7R, ±10%, SMD 0805; Manufacturer: YAGEO; Manufacturer Part Number: CC0805KKX7R9BB334
footprint CAP-0805 (0805 (2012M) Capacitor)
pins: 1, 2

## CC0805KKX7R9BB474
designator C?  Capacitance: 470nF  (hidden comment: *)
Capacitor, Ceramic (MLCC), 470nF, ±10%, 50V, X7R, ±10%, SMD 0805; Manufacturer: YAGEO; Manufacturer Part Number: CC0805KKX7R9BB474
footprint CAP-0805 (0805 (2012M) Capacitor)
pins: 1, 2

## CC0805KKX7R9BB684
designator C?  Capacitance: 680nF  (hidden comment: *)
Capacitor, Ceramic (MLCC), 680nF, ±10%, 50V, X7R, ±10%, SMD 0805; Manufacturer: YAGEO; Manufacturer Part Number: CC0805KKX7R9BB684
footprint CAP-0805 (0805 (2012M) Capacitor)
pins: 1, 2

## CC0805KKX7RABB103
designator C?  Capacitance: 10nF  (hidden comment: *)
Capacitor, Ceramic (MLCC), 10nF, ±10%, 200V, X7R, ±10%, SMD 0805; Manufacturer: YAGEO; Manufacturer Part Number: CC0805KKX7RABB103
footprint CAP-0805 (0805 (2012M) Capacitor)
pins: 1, 2

## CC0805KKX7RABB223
designator C?  Capacitance: 22nF  (hidden comment: *)
Capacitor, Ceramic (MLCC), 22nF, ±10%, 200V, X7R, ±10%, SMD 0805; Manufacturer: YAGEO; Manufacturer Part Number: CC0805KKX7RABB223
footprint CAP-0805 (0805 (2012M) Capacitor)
pins: 1, 2

## CC0805KKX7RABB682
designator C?  Capacitance: 6.8nF  (hidden comment: *)
Capacitor, Ceramic (MLCC), 6.8nF, ±10%, 200V, X7R, ±10%, SMD 0805; Manufacturer: YAGEO; Manufacturer Part Number: CC0805KKX7RABB682
footprint CAP-0805 (0805 (2012M) Capacitor)
pins: 1, 2

## CC0805KKX7RBBB103
designator C?  Capacitance: 10nF  (hidden comment: *)
Capacitor, Ceramic (MLCC), 10nF, ±10%, 500V, X7R, ±10%, SMD 0805; Manufacturer: YAGEO; Manufacturer Part Number: CC0805KKX7RBBB103
footprint CAP-0805 (0805 (2012M) Capacitor)
pins: 1, 2

## CC0805KKX7RYBB103
designator C?  Capacitance: 10nF  (hidden comment: *)
Capacitor, Ceramic (MLCC), 10nF, ±10%, 250V, X7R, ±10%, SMD 0805; Manufacturer: YAGEO; Manufacturer Part Number: CC0805KKX7RYBB103
footprint CAP-0805 (0805 (2012M) Capacitor)
pins: 1, 2

## CC0805KKX7RYBB223
designator C?  Capacitance: 22nF  (hidden comment: *)
Capacitor, Ceramic (MLCC), 22nF, ±10%, 250V, X7R, ±10%, SMD 0805; Manufacturer: YAGEO; Manufacturer Part Number: CC0805KKX7RYBB223
footprint CAP-0805 (0805 (2012M) Capacitor)
pins: 1, 2

## CC0805KKX7RYBB273
designator C?  Capacitance: 27nF  (hidden comment: *)
Capacitor, Ceramic (MLCC), 27nF, ±10%, 250V, X7R, ±10%, SMD 0805; Manufacturer: YAGEO; Manufacturer Part Number: CC0805KKX7RYBB273
footprint CAP-0805 (0805 (2012M) Capacitor)
pins: 1, 2

## CC0805KRNPO0BN471
designator C?  Capacitance: 470pF  (hidden comment: *)
Capacitor, Ceramic (MLCC), 470pF, ±10%, 100V, NP0, ±10%, SMD 0805; Manufacturer: YAGEO; Manufacturer Part Number: CC0805KRNPO0BN471
footprint CAP-0805 (0805 (2012M) Capacitor)
pins: 1, 2

## CC0805KRX5R5BB225
designator C?  Capacitance: 2.2uF  (hidden comment: *)
Capacitor, Ceramic (MLCC), 2.2uF, ±10%, 6.3V, X5R, ±10%, SMD 0805; Manufacturer: YAGEO; Manufacturer Part Number: CC0805KRX5R5BB225
footprint CAP-0805 (0805 (2012M) Capacitor)
pins: 1, 2

## CC0805KRX5R6BB106
designator C?  Capacitance: 10uF  (hidden comment: *)
Capacitor, Ceramic (MLCC), 10uF, ±10%, 10V, X5R, ±10%, SMD 0805; Manufacturer: YAGEO; Manufacturer Part Number: CC0805KRX5R6BB106
footprint CAP-0805 (0805 (2012M) Capacitor)
pins: 1, 2

## CC0805KRX5R6BB225
designator C?  Capacitance: 2.2uF  (hidden comment: *)
Capacitor, Ceramic (MLCC), 2.2uF, ±10%, 10V, X5R, ±10%, SMD 0805; Manufacturer: YAGEO; Manufacturer Part Number: CC0805KRX5R6BB225
footprint CAP-0805 (0805 (2012M) Capacitor)
pins: 1, 2

## CC0805KRX5R7BB225
designator C?  Capacitance: 2.2uF  (hidden comment: *)
Capacitor, Ceramic (MLCC), 2.2uF, ±10%, 16V, X5R, ±10%, SMD 0805; Manufacturer: YAGEO; Manufacturer Part Number: CC0805KRX5R7BB225
footprint CAP-0805 (0805 (2012M) Capacitor)
pins: 1, 2

## CC0805KRX7R0BB103
designator C?  Capacitance: 10nF  (hidden comment: *)
Capacitor, Ceramic (MLCC), 10nF, ±10%, 100V, X7R, ±10%, SMD 0805; Manufacturer: YAGEO; Manufacturer Part Number: CC0805KRX7R0BB103
footprint CAP-0805 (0805 (2012M) Capacitor)
pins: 1, 2

## CC0805KRX7R0BB123
designator C?  Capacitance: 12nF  (hidden comment: *)
Capacitor, Ceramic (MLCC), 12nF, ±10%, 100V, X7R, ±10%, SMD 0805; Manufacturer: YAGEO; Manufacturer Part Number: CC0805KRX7R0BB123
footprint CAP-0805 (0805 (2012M) Capacitor)
pins: 1, 2

## CC0805KRX7R0BB152
designator C?  Capacitance: 1.5nF  (hidden comment: *)
Capacitor, Ceramic (MLCC), 1.5nF, ±10%, 100V, X7R, ±10%, SMD 0805; Manufacturer: YAGEO; Manufacturer Part Number: CC0805KRX7R0BB152
footprint CAP-0805 (0805 (2012M) Capacitor)
pins: 1, 2

## CC0805KRX7R0BB182
designator C?  Capacitance: 1.8nF  (hidden comment: *)
Capacitor, Ceramic (MLCC), 1.8nF, ±10%, 100V, X7R, ±10%, SMD 0805; Manufacturer: YAGEO; Manufacturer Part Number: CC0805KRX7R0BB182
footprint CAP-0805 (0805 (2012M) Capacitor)
pins: 1, 2

## CC0805KRX7R0BB221
designator C?  Capacitance: 220pF  (hidden comment: *)
Capacitor, Ceramic (MLCC), 220pF, ±10%, 100V, X7R, ±10%, SMD 0805; Manufacturer: YAGEO; Manufacturer Part Number: CC0805KRX7R0BB221
footprint CAP-0805 (0805 (2012M) Capacitor)
pins: 1, 2

## CC0805KRX7R0BB222
designator C?  Capacitance: 2.2nF  (hidden comment: *)
Capacitor, Ceramic (MLCC), 2.2nF, ±10%, 100V, X7R, ±10%, SMD 0805; Manufacturer: YAGEO; Manufacturer Part Number: CC0805KRX7R0BB222
footprint CAP-0805 (0805 (2012M) Capacitor)
pins: 1, 2

## CC0805KRX7R0BB223
designator C?  Capacitance: 22nF  (hidden comment: *)
Capacitor, Ceramic (MLCC), 22nF, ±10%, 100V, X7R, ±10%, SMD 0805; Manufacturer: YAGEO; Manufacturer Part Number: CC0805KRX7R0BB223
footprint CAP-0805 (0805 (2012M) Capacitor)
pins: 1, 2

## CC0805KRX7R0BB272
designator C?  Capacitance: 2.7nF  (hidden comment: *)
Capacitor, Ceramic (MLCC), 2.7nF, ±10%, 100V, X7R, ±10%, SMD 0805; Manufacturer: YAGEO; Manufacturer Part Number: CC0805KRX7R0BB272
footprint CAP-0805 (0805 (2012M) Capacitor)
pins: 1, 2

## CC0805KRX7R0BB331
designator C?  Capacitance: 330pF  (hidden comment: *)
Capacitor, Ceramic (MLCC), 330pF, ±10%, 100V, X7R, ±10%, SMD 0805; Manufacturer: YAGEO; Manufacturer Part Number: CC0805KRX7R0BB331
footprint CAP-0805 (0805 (2012M) Capacitor)
pins: 1, 2

## CC0805KRX7R0BB332
designator C?  Capacitance: 3.3nF  (hidden comment: *)
Capacitor, Ceramic (MLCC), 3.3nF, ±10%, 100V, X7R, ±10%, SMD 0805; Manufacturer: YAGEO; Manufacturer Part Number: CC0805KRX7R0BB332
footprint CAP-0805 (0805 (2012M) Capacitor)
pins: 1, 2

## CC0805KRX7R0BB471
designator C?  Capacitance: 470pF  (hidden comment: *)
Capacitor, Ceramic (MLCC), 470pF, ±10%, 100V, X7R, ±10%, SMD 0805; Manufacturer: YAGEO; Manufacturer Part Number: CC0805KRX7R0BB471
footprint CAP-0805 (0805 (2012M) Capacitor)
pins: 1, 2

## CC0805KRX7R0BB472
designator C?  Capacitance: 4.7nF  (hidden comment: *)
Capacitor, Ceramic (MLCC), 4.7nF, ±10%, 100V, X7R, ±10%, SMD 0805; Manufacturer: YAGEO; Manufacturer Part Number: CC0805KRX7R0BB472
footprint CAP-0805 (0805 (2012M) Capacitor)
pins: 1, 2

## CC0805KRX7R0BB682
designator C?  Capacitance: 6.8nF  (hidden comment: *)
Capacitor, Ceramic (MLCC), 6.8nF, ±10%, 100V, X7R, ±10%, SMD 0805; Manufacturer: YAGEO; Manufacturer Part Number: CC0805KRX7R0BB682
footprint CAP-0805 (0805 (2012M) Capacitor)
pins: 1, 2

## CC0805KRX7R0BB821
designator C?  Capacitance: 820pF  (hidden comment: *)
Capacitor, Ceramic (MLCC), 820pF, ±10%, 100V, X7R, ±10%, SMD 0805; Manufacturer: YAGEO; Manufacturer Part Number: CC0805KRX7R0BB821
footprint CAP-0805 (0805 (2012M) Capacitor)
pins: 1, 2

## CC0805KRX7R0BB822
designator C?  Capacitance: 8.2nF  (hidden comment: *)
Capacitor, Ceramic (MLCC), 8.2nF, ±10%, 100V, X7R, ±10%, SMD 0805; Manufacturer: YAGEO; Manufacturer Part Number: CC0805KRX7R0BB822
footprint CAP-0805 (0805 (2012M) Capacitor)
pins: 1, 2

## CC0805KRX7R6BB224
designator C?  Capacitance: 220nF  (hidden comment: *)
Capacitor, Ceramic (MLCC), 220nF, ±10%, 10V, X7R, ±10%, SMD 0805; Manufacturer: YAGEO; Manufacturer Part Number: CC0805KRX7R6BB224
footprint CAP-0805 (0805 (2012M) Capacitor)
pins: 1, 2

## CC0805KRX7R7BB103
designator C?  Capacitance: 10nF  (hidden comment: *)
Capacitor, Ceramic (MLCC), 10nF, ±10%, 16V, X7R, ±10%, SMD 0805; Manufacturer: YAGEO; Manufacturer Part Number: CC0805KRX7R7BB103
footprint CAP-0805 (0805 (2012M) Capacitor)
pins: 1, 2

## CC0805KRX7R7BB104
designator C?  Capacitance: 100nF  (hidden comment: *)
Capacitor, Ceramic (MLCC), 100nF, ±10%, 16V, X7R, ±10%, SMD 0805; Manufacturer: YAGEO; Manufacturer Part Number: CC0805KRX7R7BB104
footprint CAP-0805 (0805 (2012M) Capacitor)
pins: 1, 2

## CC0805KRX7R7BB154
designator C?  Capacitance: 150nF  (hidden comment: *)
Capacitor, Ceramic (MLCC), 150nF, ±10%, 16V, X7R, ±10%, SMD 0805; Manufacturer: YAGEO; Manufacturer Part Number: CC0805KRX7R7BB154
footprint CAP-0805 (0805 (2012M) Capacitor)
pins: 1, 2

## CC0805KRX7R7BB184
designator C?  Capacitance: 180nF  (hidden comment: *)
Capacitor, Ceramic (MLCC), 180nF, ±10%, 16V, X7R, ±10%, SMD 0805; Manufacturer: YAGEO; Manufacturer Part Number: CC0805KRX7R7BB184
footprint CAP-0805 (0805 (2012M) Capacitor)
pins: 1, 2

## CC0805KRX7R7BB223
designator C?  Capacitance: 22nF  (hidden comment: *)
Capacitor, Ceramic (MLCC), 22nF, ±10%, 16V, X7R, ±10%, SMD 0805; Manufacturer: YAGEO; Manufacturer Part Number: CC0805KRX7R7BB223
footprint CAP-0805 (0805 (2012M) Capacitor)
pins: 1, 2

## CC0805KRX7R7BB224
designator C?  Capacitance: 220nF  (hidden comment: *)
Capacitor, Ceramic (MLCC), 220nF, ±10%, 16V, X7R, ±10%, SMD 0805; Manufacturer: YAGEO; Manufacturer Part Number: CC0805KRX7R7BB224
footprint CAP-0805 (0805 (2012M) Capacitor)
pins: 1, 2

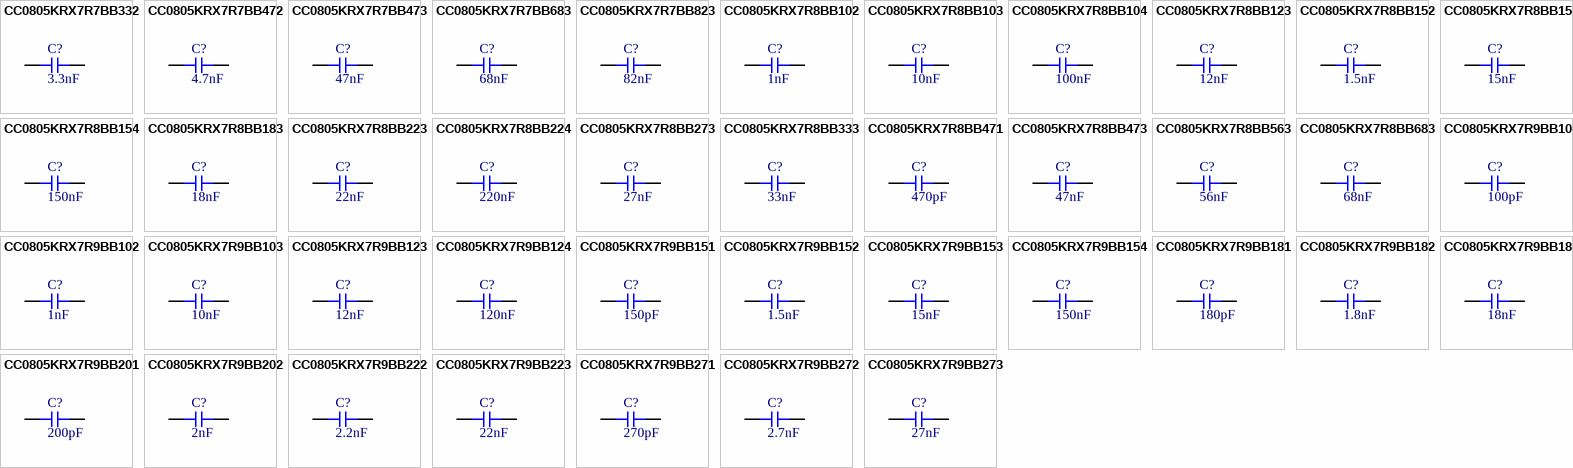
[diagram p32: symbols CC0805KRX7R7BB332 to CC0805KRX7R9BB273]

## CC0805KRX7R7BB332
designator C?  Capacitance: 3.3nF  (hidden comment: *)
Capacitor, Ceramic (MLCC), 3.3nF, ±10%, 16V, X7R, ±10%, SMD 0805; Manufacturer: YAGEO; Manufacturer Part Number: CC0805KRX7R7BB332
footprint CAP-0805 (0805 (2012M) Capacitor)
pins: 1, 2

## CC0805KRX7R7BB472
designator C?  Capacitance: 4.7nF  (hidden comment: *)
Capacitor, Ceramic (MLCC), 4.7nF, ±10%, 16V, X7R, ±10%, SMD 0805; Manufacturer: YAGEO; Manufacturer Part Number: CC0805KRX7R7BB472
footprint CAP-0805 (0805 (2012M) Capacitor)
pins: 1, 2

## CC0805KRX7R7BB473
designator C?  Capacitance: 47nF  (hidden comment: *)
Capacitor, Ceramic (MLCC), 47nF, ±10%, 16V, X7R, ±10%, SMD 0805; Manufacturer: YAGEO; Manufacturer Part Number: CC0805KRX7R7BB473
footprint CAP-0805 (0805 (2012M) Capacitor)
pins: 1, 2

## CC0805KRX7R7BB683
designator C?  Capacitance: 68nF  (hidden comment: *)
Capacitor, Ceramic (MLCC), 68nF, ±10%, 16V, X7R, ±10%, SMD 0805; Manufacturer: YAGEO; Manufacturer Part Number: CC0805KRX7R7BB683
footprint CAP-0805 (0805 (2012M) Capacitor)
pins: 1, 2

## CC0805KRX7R7BB823
designator C?  Capacitance: 82nF  (hidden comment: *)
Capacitor, Ceramic (MLCC), 82nF, ±10%, 16V, X7R, ±10%, SMD 0805; Manufacturer: YAGEO; Manufacturer Part Number: CC0805KRX7R7BB823
footprint CAP-0805 (0805 (2012M) Capacitor)
pins: 1, 2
